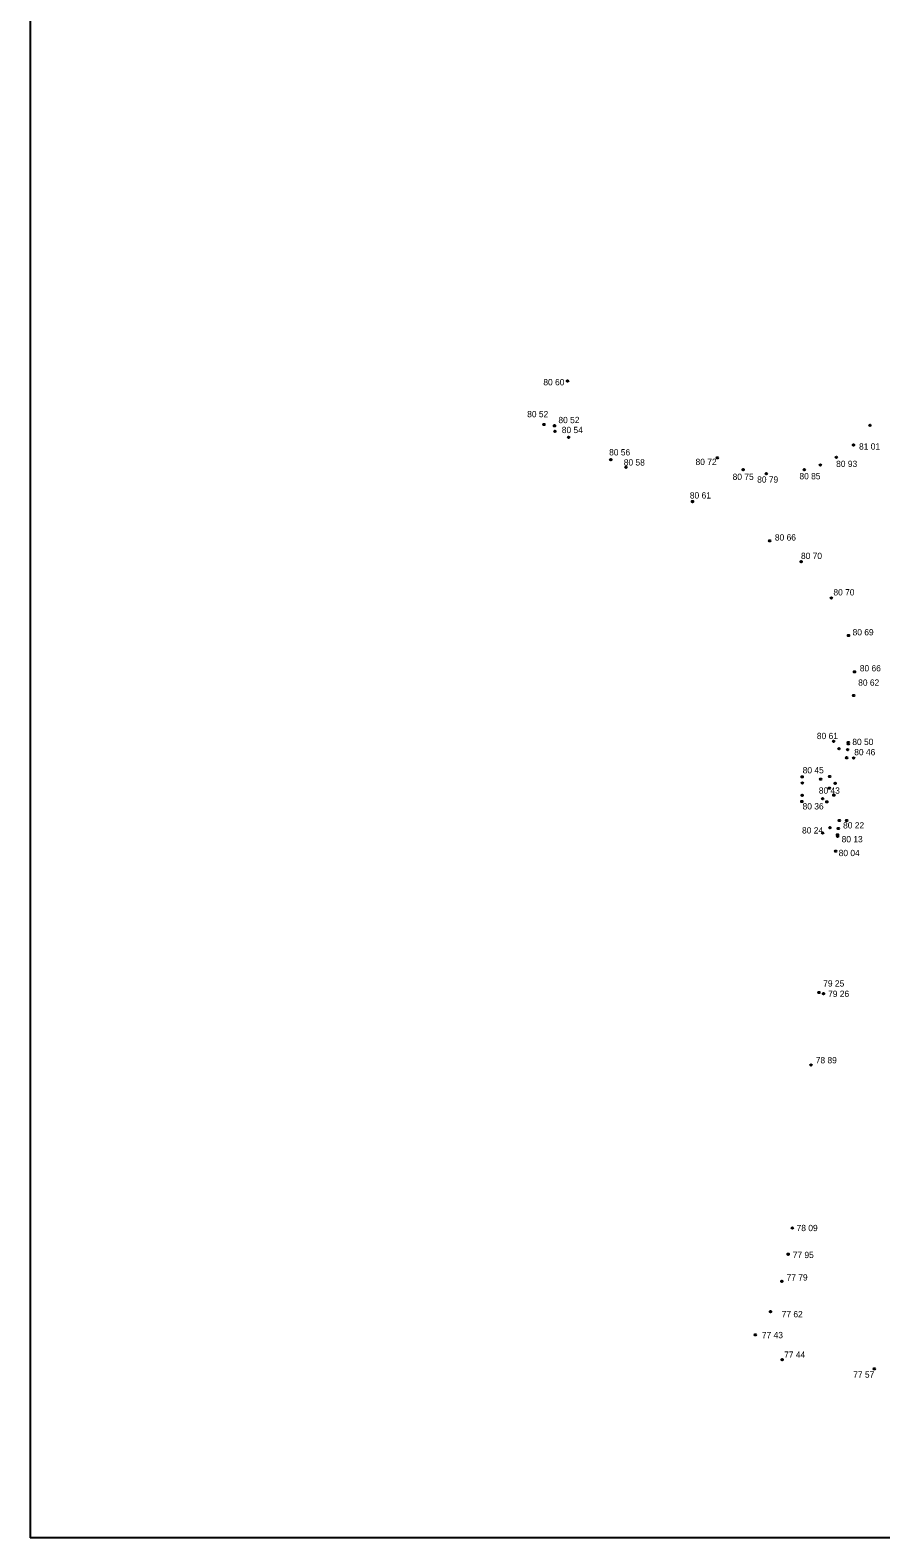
# Model space of a CAD drawing. Extents: x -602085 to -601979, y -1162698 to -1162507.
# Drawn here: x -602085.1 to -602031, y -1162698.5 to -1162602.6 of the extents above; entities that cross this region are included whole.
import ezdxf

# ---------------------------------------------------------------- set-up
doc = ezdxf.new("R2010")
doc.units = 0
for name, color, linetype in [('Okraj', 7, 'Continuous'), ('Vrstva 58', 7, 'Continuous'), ('Vrstva 60', 7, 'Continuous')]:
    doc.layers.add(name, color=color, linetype=linetype)

msp = doc.modelspace()

# ---------------------------------------------------------------- linework, layer by layer
at = {"layer": 'Okraj'}
for p, q in [((-602085.131, -1162549.983), (-602085.131, -1162624.233)), ((-602085.131, -1162624.233), (-602085.131, -1162698.483)), ((-602032.631, -1162698.483), (-602085.131, -1162698.483)), ((-601980.131, -1162698.483), (-602032.631, -1162698.483))]:
    msp.add_line(p, q, dxfattribs=at)
at = {"layer": 'Vrstva 60'}
for centre in [(-602050.95, -1162624.89), (-602052.45, -1162627.66), (-602051.78, -1162627.74), (-602031.71, -1162627.71), (-602051.75, -1162628.09), (-602050.88, -1162628.48), (-602041.42, -1162629.78), (-602033.85, -1162629.75), (-602032.76, -1162628.96), (-602048.2, -1162629.89), (-602047.23, -1162630.39), (-602039.78, -1162630.53), (-602038.31, -1162630.78), (-602035.89, -1162630.53), (-602034.87, -1162630.24), (-602043, -1162632.56), (-602038.1, -1162635.06), (-602036.09, -1162636.39), (-602034.17, -1162638.7), (-602033.08, -1162641.08), (-602032.7, -1162643.39), (-602032.75, -1162644.9), (-602034.03, -1162647.82), (-602033.09, -1162647.89), (-602033.09, -1162647.97), (-602033.68, -1162648.28), (-602033.2, -1162648.86), (-602033.13, -1162648.35), (-602032.75, -1162648.88), (-602036.03, -1162650.07), (-602036.01, -1162650.47), (-602034.85, -1162650.22), (-602034.3, -1162650.79), (-602034.28, -1162650.05), (-602033.93, -1162650.49), (-602036.05, -1162651.64), (-602036.03, -1162651.25), (-602034.72, -1162651.46), (-602034.46, -1162651.66), (-602034.01, -1162651.24), (-602033.66, -1162652.85), (-602033.19, -1162652.85), (-602034.72, -1162653.64), (-602034.26, -1162653.3), (-602033.78, -1162653.76), (-602033.72, -1162653.36), (-602033.77, -1162653.85), (-602033.89, -1162654.8), (-602034.95, -1162663.79), (-602034.67, -1162663.86), (-602035.46, -1162668.41), (-602036.65, -1162678.77), (-602036.92, -1162680.44), (-602037.32, -1162682.16), (-602038.04, -1162684.09), (-602039.01, -1162685.57), (-602037.3, -1162687.15), (-602031.43, -1162687.73)]:
    msp.add_circle(centre, 0.05, dxfattribs=at)

# ---------------------------------------------------------------- texts
at = {"layer": 'Vrstva 58'}
for s, p in [('80 60', (-602052.489, -1162625.166)), ('80 52', (-602053.517, -1162627.198)), ('80 52', (-602051.531, -1162627.573)), ('80 54', (-602051.315, -1162628.206)), ('80 56', (-602048.304, -1162629.627)), ('81 01', (-602032.41, -1162629.255)), ('80 58', (-602047.373, -1162630.268)), ('80 72', (-602042.808, -1162630.238)), ('80 85', (-602036.2, -1162631.146)), ('80 93', (-602033.865, -1162630.361)), ('80 75', (-602040.45, -1162631.185)), ('80 79', (-602038.889, -1162631.358)), ('80 61', (-602043.169, -1162632.367)), ('80 66', (-602037.761, -1162635.041)), ('80 70', (-602036.102, -1162636.217)), ('80 70', (-602034.04, -1162638.533)), ('80 69', (-602032.819, -1162641.074)), ('80 66', (-602032.361, -1162643.364)), ('80 62', (-602032.463, -1162644.277)), ('80 61', (-602035.092, -1162647.672)), ('80 50', (-602032.838, -1162648.051)), ('80 46', (-602032.716, -1162648.699)), ('80 45', (-602035.993, -1162649.852)), ('80 43', (-602034.968, -1162651.146)), ('80 36', (-602036, -1162652.147)), ('80 24', (-602036.037, -1162653.677)), ('80 22', (-602033.425, -1162653.356)), ('80 04', (-602033.704, -1162655.116)), ('80 13', (-602033.514, -1162654.24)), ('79 25', (-602034.687, -1162663.412)), ('79 26', (-602034.377, -1162664.074)), ('78 89', (-602035.163, -1162668.298)), ('78 09', (-602036.38, -1162678.972)), ('77 95', (-602036.628, -1162680.687)), ('77 79', (-602037.017, -1162682.115)), ('77 62', (-602037.329, -1162684.456)), ('77 43', (-602038.588, -1162685.782)), ('77 44', (-602037.173, -1162687.028)), ('77 57', (-602032.78, -1162688.295))]:
    msp.add_text(s, height=0.4, dxfattribs=at).set_placement(p)

doc.saveas('drawing.dxf')
